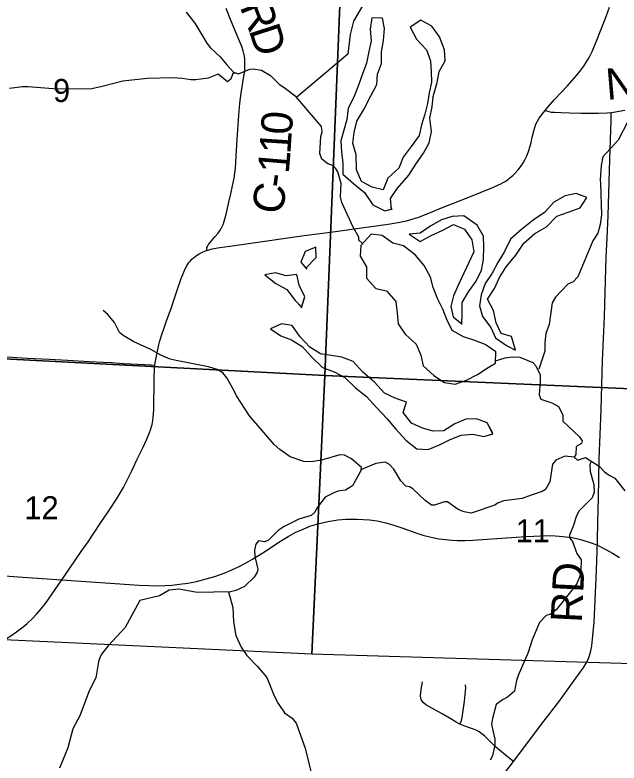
# Model space of a CAD drawing. Extents: x 0 to 34, y 0 to 22.
# Drawn here: x 4.017 to 5.115, y 17.641 to 19.003 of the extents above; entities that cross this region are included whole.
import ezdxf

# ---------------------------------------------------------------- set-up
doc = ezdxf.new("R2010")
doc.units = 0
for name, color, linetype in [('GM_X_County_Road', 7, 'Continuous'), ('GM_X_County_Road_Text', 7, 'Continuous'), ('GM_X_Minor_Lake', 7, 'Continuous'), ('GM_X_Minor_River', 7, 'Continuous'), ('GM_X_Rail_Line', 7, 'Continuous'), ('GM_X_Section', 7, 'Continuous'), ('GM_X_Section_Text', 7, 'Continuous'), ('GM_X_State_Route', 7, 'Continuous'), ('GM_X_Township_Road', 7, 'Continuous')]:
    doc.layers.add(name, color=color, linetype=linetype)

msp = doc.modelspace()

# ---------------------------------------------------------------- linework, layer by layer
at = {"layer": 'GM_X_County_Road'}
for points in [[(4.3655, 18.5744), (4.3655, 18.5774), (4.3658, 18.5797), (4.3666, 18.5814), (4.3689, 18.5853), (4.374, 18.5919), (4.3802, 18.5989), (4.3861, 18.606), (4.3896, 18.611), (4.3926, 18.6157), (4.3953, 18.6216), (4.398, 18.6295), (4.401, 18.6401), (4.4059, 18.6625), (4.4094, 18.6776), (4.4123, 18.6919), (4.4151, 18.7059), (4.4165, 18.7151), (4.4178, 18.7239), (4.4185, 18.7345), (4.419, 18.7462), (4.4207, 18.7772), (4.4236, 18.8206), (4.4255, 18.8423), (4.4278, 18.8608), (4.4327, 18.8915), (4.4345, 18.9017), (4.435, 18.9099), (4.435, 18.916), (4.4348, 18.9237), (4.4336, 18.9308), (4.4318, 18.9375), (4.4291, 18.9456), (4.4239, 18.9587), (4.4099, 18.9919), (4.4008, 19.0151)], [(4.9808, 18.8289), (4.9877, 18.8273), (4.9918, 18.8263), (4.9978, 18.8259), (5.0104, 18.8253), (5.0256, 18.8251), (5.0461, 18.8243), (5.0651, 18.8243), (5.0783, 18.8245), (5.0939, 18.8251), (5.101, 18.8258)], [(5.101, 18.8258), (5.1057, 18.8263), (5.126, 18.8297)], [(5.0762, 18.0453), (5.0771, 18.0802), (5.078, 18.123), (5.0796, 18.1943), (5.0828, 18.2841), (5.0855, 18.3739), (5.0888, 18.4539), (5.092, 18.5618), (5.094, 18.5969), (5.0956, 18.6378), (5.0986, 18.74), (5.1013, 18.8108), (5.1011, 18.822), (5.101, 18.8258)], [(4.9235, 17.6434), (4.9789, 17.7169), (5.0059, 17.7525), (5.0448, 17.8062), (5.0503, 17.8138), (5.0553, 17.8216), (5.0582, 17.8271), (5.0606, 17.8329), (5.0625, 17.8388), (5.064, 17.8449), (5.0657, 17.854), (5.0681, 17.8724), (5.0704, 17.8971), (5.0741, 17.9775), (5.0753, 18.0085), (5.0762, 18.0453)], [(4.9075, 17.6233), (4.9235, 17.6434)]]:
    msp.add_lwpolyline(points, dxfattribs=at)
at = {"layer": 'GM_X_Minor_Lake'}
for points in [[(4.7016, 18.6496), (4.6999, 18.6686), (4.7124, 18.6879), (4.7332, 18.7111), (4.7461, 18.7312), (4.7597, 18.7513), (4.7703, 18.7703), (4.7741, 18.7908), (4.7714, 18.8154), (4.7756, 18.8359), (4.7775, 18.8549), (4.7847, 18.8799), (4.7881, 18.9), (4.7994, 18.9198), (4.7979, 18.9395), (4.7888, 18.9634), (4.7748, 18.9827), (4.7552, 18.9937), (4.7355, 18.9808), (4.7472, 18.9592), (4.7654, 18.9395), (4.7726, 18.9194), (4.7737, 18.8996), (4.7744, 18.8807), (4.7703, 18.8613), (4.7673, 18.842), (4.762, 18.8226), (4.7559, 18.8029), (4.7521, 18.7835), (4.7374, 18.7634), (4.7226, 18.7441), (4.7147, 18.724), (4.695, 18.7058), (4.6863, 18.6849), (4.6666, 18.6894), (4.6469, 18.6997), (4.6378, 18.7213), (4.6371, 18.7482), (4.6314, 18.7699), (4.6337, 18.7892), (4.6382, 18.8097), (4.6511, 18.8309), (4.664, 18.8556), (4.6746, 18.8765), (4.6761, 18.8955), (4.6833, 18.9148), (4.6836, 18.9357), (4.6867, 18.9565), (4.6889, 18.9782), (4.6852, 18.9971), (4.6659, 18.9979), (4.6625, 18.977), (4.6647, 18.9562), (4.6606, 18.9364), (4.656, 18.9152), (4.6481, 18.8939), (4.6416, 18.875), (4.6329, 18.8537), (4.6227, 18.8332), (4.6204, 18.8127), (4.6151, 18.7934), (4.6091, 18.774), (4.6106, 18.7539), (4.6129, 18.7334), (4.6129, 18.7133), (4.6322, 18.6963), (4.6526, 18.6799), (4.6673, 18.6576), (4.6893, 18.6466)], [(4.7018, 18.6481), (4.6999, 18.6686), (4.7124, 18.6879), (4.7332, 18.7111), (4.7461, 18.7312), (4.7597, 18.7513), (4.7703, 18.7703), (4.7741, 18.7908), (4.7714, 18.8154), (4.7756, 18.8359), (4.7775, 18.8549), (4.7847, 18.8799), (4.7881, 18.9), (4.7994, 18.9198), (4.7979, 18.9395), (4.7888, 18.9634), (4.7748, 18.9827), (4.7552, 18.9937), (4.7355, 18.9808), (4.7472, 18.9592), (4.7654, 18.9395), (4.7726, 18.9194), (4.7737, 18.8996), (4.7744, 18.8807), (4.7703, 18.8613), (4.7673, 18.842), (4.762, 18.8226), (4.7559, 18.8029), (4.7521, 18.7835), (4.7374, 18.7634), (4.7226, 18.7441), (4.7147, 18.724), (4.695, 18.7058), (4.6863, 18.6849), (4.6666, 18.6894), (4.6469, 18.6997), (4.6378, 18.7213), (4.6371, 18.7482), (4.6314, 18.7699), (4.6337, 18.7892), (4.6382, 18.8097), (4.6511, 18.8309), (4.664, 18.8556), (4.6746, 18.8765), (4.6761, 18.8955), (4.6833, 18.9148), (4.6836, 18.9357), (4.6867, 18.9565), (4.6889, 18.9782), (4.6852, 18.9971), (4.6659, 18.9979), (4.6625, 18.977), (4.6647, 18.9562), (4.6606, 18.9364), (4.656, 18.9152), (4.6481, 18.8939), (4.6416, 18.875), (4.6329, 18.8537), (4.6227, 18.8332), (4.6204, 18.8127), (4.6151, 18.7934), (4.6091, 18.774), (4.6106, 18.7539), (4.6129, 18.7334), (4.6129, 18.7133), (4.6322, 18.6963), (4.6526, 18.6799), (4.6673, 18.6576), (4.6893, 18.6466), (4.7033, 18.65)], [(5.0374, 18.6777), (5.0177, 18.6736), (4.9969, 18.6622), (4.9799, 18.6432), (4.9595, 18.6295), (4.9383, 18.6125), (4.9182, 18.5946), (4.9069, 18.5722), (4.8951, 18.5525), (4.8849, 18.5332), (4.872, 18.5142), (4.8648, 18.4937), (4.8618, 18.4732), (4.8671, 18.4542), (4.8823, 18.4341), (4.8906, 18.4152), (4.911, 18.4015), (4.9269, 18.3928)], [(4.9269, 18.3928), (4.9201, 18.4178), (4.9008, 18.4231), (4.8921, 18.4425), (4.8872, 18.4649), (4.8762, 18.4857), (4.8887, 18.5051), (4.8982, 18.5252), (4.9099, 18.5442), (4.9277, 18.5658), (4.942, 18.5874), (4.9621, 18.6053), (4.9837, 18.6174), (5.0022, 18.6368), (5.023, 18.644), (5.0446, 18.6516), (5.0567, 18.6705), (5.0374, 18.6777), (5.0177, 18.6736), (4.9969, 18.6622), (4.9799, 18.6432), (4.9595, 18.6295), (4.9383, 18.6125), (4.9182, 18.5946), (4.9069, 18.5722), (4.8951, 18.5525), (4.8849, 18.5332), (4.872, 18.5142), (4.8648, 18.4937), (4.8618, 18.4732), (4.8671, 18.4542), (4.8823, 18.4341), (4.8906, 18.4152), (4.911, 18.4015), (4.9269, 18.3928)], [(4.9269, 18.3928), (4.9201, 18.4178), (4.9008, 18.4231), (4.8921, 18.4425), (4.8872, 18.4649), (4.8762, 18.4857), (4.8887, 18.5051), (4.8982, 18.5252), (4.9099, 18.5442), (4.9277, 18.5658), (4.942, 18.5874), (4.9621, 18.6053), (4.9837, 18.6174), (5.0022, 18.6368), (5.023, 18.644), (5.0446, 18.6516), (5.0567, 18.6705), (5.0374, 18.6777)], [(4.6893, 18.6466), (4.7016, 18.6496)], [(4.8297, 18.4405), (4.83, 18.458), (4.8304, 18.4793), (4.8418, 18.499), (4.8558, 18.5184), (4.8652, 18.5381), (4.869, 18.5578), (4.8698, 18.5806), (4.869, 18.6003), (4.8573, 18.6204), (4.8331, 18.6371), (4.8119, 18.636), (4.7926, 18.6299), (4.7733, 18.6193), (4.7536, 18.606), (4.7339, 18.6037), (4.7536, 18.5904), (4.774, 18.6014), (4.7952, 18.6113), (4.8145, 18.6215), (4.8342, 18.6132), (4.8475, 18.5939), (4.8512, 18.5715), (4.8425, 18.5525), (4.8334, 18.5328), (4.8236, 18.5123), (4.8141, 18.4918), (4.8092, 18.4724), (4.8138, 18.4531)], [(4.8297, 18.4414), (4.83, 18.458), (4.8304, 18.4793), (4.8418, 18.499), (4.8558, 18.5184), (4.8652, 18.5381), (4.869, 18.5578), (4.8698, 18.5806), (4.869, 18.6003), (4.8573, 18.6204), (4.8331, 18.6371), (4.8119, 18.636), (4.7926, 18.6299), (4.7733, 18.6193), (4.7536, 18.606), (4.7339, 18.6037), (4.7536, 18.5904), (4.774, 18.6014), (4.7952, 18.6113), (4.8145, 18.6215), (4.8342, 18.6132), (4.8475, 18.5939), (4.8512, 18.5715), (4.8425, 18.5525), (4.8334, 18.5328), (4.8236, 18.5123), (4.8141, 18.4918), (4.8092, 18.4724), (4.8138, 18.4531), (4.83, 18.4402)], [(4.8913, 18.3894), (4.8717, 18.403), (4.8516, 18.411), (4.8323, 18.4167), (4.8119, 18.4284), (4.802, 18.4485), (4.7948, 18.4675), (4.785, 18.4869), (4.7771, 18.507), (4.7725, 18.5259), (4.7608, 18.5468), (4.7453, 18.5658), (4.7233, 18.5828), (4.7037, 18.5874), (4.6844, 18.6018), (4.6647, 18.6037), (4.6458, 18.5836), (4.6443, 18.5639), (4.656, 18.5445), (4.656, 18.524), (4.673, 18.505), (4.6927, 18.5005), (4.7097, 18.4815), (4.7116, 18.4603), (4.7135, 18.4409), (4.7267, 18.422), (4.7464, 18.4034), (4.7551, 18.3833), (4.7593, 18.3643), (4.7786, 18.3465), (4.7982, 18.334), (4.8175, 18.3306), (4.838, 18.3378), (4.8577, 18.3484), (4.8773, 18.3613), (4.8906, 18.3693)], [(4.8906, 18.3693), (4.8913, 18.3894), (4.8717, 18.403), (4.8516, 18.411), (4.8323, 18.4167), (4.8119, 18.4284), (4.802, 18.4485), (4.7948, 18.4675), (4.785, 18.4869), (4.7771, 18.507), (4.7725, 18.5259), (4.7608, 18.5468), (4.7453, 18.5658), (4.7233, 18.5828), (4.7037, 18.5874), (4.6844, 18.6018), (4.6647, 18.6037), (4.6458, 18.5836), (4.6443, 18.5639), (4.656, 18.5445), (4.656, 18.524), (4.673, 18.505), (4.6927, 18.5005), (4.7097, 18.4815), (4.7116, 18.4603), (4.7135, 18.4409), (4.7267, 18.422), (4.7464, 18.4034), (4.7551, 18.3833), (4.7593, 18.3643), (4.7786, 18.3465), (4.7982, 18.334), (4.8175, 18.3306), (4.838, 18.3378), (4.8577, 18.3484), (4.8773, 18.3613), (4.8906, 18.3693), (4.8906, 18.3707)], [(4.5458, 18.5422), (4.5648, 18.5616), (4.564, 18.5805), (4.5444, 18.5722), (4.5368, 18.5532)], [(4.5451, 18.5414), (4.5648, 18.5616), (4.564, 18.5805), (4.5444, 18.5722), (4.5368, 18.5532), (4.5474, 18.5403)], [(4.5368, 18.5532), (4.5458, 18.5422)], [(4.5436, 18.4898), (4.5334, 18.5111), (4.5296, 18.5304), (4.5099, 18.5282), (4.4903, 18.5335), (4.471, 18.5297), (4.491, 18.5141), (4.5114, 18.5031), (4.5262, 18.4834), (4.538, 18.4712)], [(4.5376, 18.4697), (4.5436, 18.4898), (4.5334, 18.5111), (4.5296, 18.5304), (4.5099, 18.5282), (4.4903, 18.5335), (4.471, 18.5297), (4.491, 18.5141), (4.5114, 18.5031), (4.5262, 18.4834), (4.5376, 18.4716)], [(4.538, 18.4712), (4.5436, 18.4898)], [(4.8138, 18.4531), (4.8297, 18.4405)], [(4.8861, 18.2406), (4.8758, 18.2604), (4.8561, 18.2676), (4.8365, 18.2668), (4.8168, 18.2585), (4.7967, 18.2459), (4.7774, 18.2452), (4.7581, 18.2509), (4.7377, 18.2596), (4.7226, 18.2789), (4.729, 18.2983), (4.7082, 18.3051), (4.6889, 18.3146), (4.6707, 18.3343), (4.6495, 18.3529), (4.6321, 18.3719), (4.6113, 18.3798), (4.592, 18.3832), (4.5724, 18.3863), (4.5531, 18.3984), (4.5345, 18.4174), (4.5209, 18.4375), (4.5016, 18.4409), (4.4812, 18.4314), (4.5005, 18.4189), (4.5198, 18.4113), (4.5391, 18.3992), (4.5568, 18.3798), (4.5761, 18.3612), (4.5973, 18.3533), (4.6166, 18.343), (4.6359, 18.3241), (4.656, 18.3081), (4.6741, 18.288), (4.6938, 18.2679), (4.7097, 18.249), (4.7275, 18.2289), (4.7479, 18.2133), (4.768, 18.2118), (4.7888, 18.2201), (4.8085, 18.23), (4.8285, 18.238), (4.8497, 18.2395), (4.8694, 18.2353)], [(4.8856, 18.2414), (4.8758, 18.2604), (4.8561, 18.2676), (4.8365, 18.2668), (4.8168, 18.2585), (4.7967, 18.2459), (4.7774, 18.2452), (4.7581, 18.2509), (4.7377, 18.2596), (4.7226, 18.2789), (4.729, 18.2983), (4.7082, 18.3051), (4.6889, 18.3146), (4.6707, 18.3343), (4.6495, 18.3529), (4.6321, 18.3719), (4.6113, 18.3798), (4.592, 18.3832), (4.5724, 18.3863), (4.5531, 18.3984), (4.5345, 18.4174), (4.5209, 18.4375), (4.5016, 18.4409), (4.4812, 18.4314), (4.5005, 18.4189), (4.5198, 18.4113), (4.5391, 18.3992), (4.5568, 18.3798), (4.5761, 18.3612), (4.5973, 18.3533), (4.6166, 18.343), (4.6359, 18.3241), (4.656, 18.3081), (4.6741, 18.288), (4.6938, 18.2679), (4.7097, 18.249), (4.7275, 18.2289), (4.7479, 18.2133), (4.768, 18.2118), (4.7888, 18.2201), (4.8085, 18.23), (4.8285, 18.238), (4.8497, 18.2395), (4.8694, 18.2353), (4.8862, 18.2406)], [(4.8906, 18.3693), (4.8913, 18.3894)], [(4.8694, 18.2353), (4.8861, 18.2406)]]:
    msp.add_lwpolyline(points, dxfattribs=at)
at = {"layer": 'GM_X_Minor_River'}
for points in [[(4.6591, 19.0379), (4.6325, 18.9919), (4.6262, 18.9675), (4.6222, 18.9318), (4.5291, 18.8535)], [(4.3278, 19.0084), (4.3438, 18.9883), (4.3656, 18.9516), (4.3717, 18.9437), (4.3899, 18.9267), (4.4017, 18.9124), (4.4143, 18.8992), (4.4234, 18.8962), (4.4441, 18.9043), (4.4498, 18.905), (4.4653, 18.9025), (4.4816, 18.8931), (4.4976, 18.8765), (4.5082, 18.8697), (4.5291, 18.8535)], [(4.4202, 18.8972), (4.4131, 18.8965), (4.409, 18.8862), (4.4034, 18.8812), (4.3863, 18.8956), (4.3678, 18.8883), (4.3459, 18.8847), (4.3364, 18.8847), (4.3209, 18.8872), (4.3035, 18.8887), (4.2569, 18.8876), (4.2127, 18.8828), (4.1753, 18.8731), (4.1564, 18.8688), (4.0936, 18.8681), (4.0403, 18.8724), (4.0304, 18.8723), (4.0066, 18.8695)], [(4.649, 18.5871), (4.6424, 18.593), (4.642, 18.5983), (4.6317, 18.6164), (4.611, 18.6615), (4.6087, 18.6717), (4.6097, 18.6964), (4.6039, 18.7173), (4.5997, 18.7244), (4.5948, 18.729), (4.5857, 18.732), (4.5751, 18.7403), (4.5709, 18.7509), (4.573, 18.7816), (4.5752, 18.7904), (4.574, 18.8002), (4.5672, 18.8085), (4.5275, 18.8548)], [(5.1312, 18.809), (5.114, 18.7751), (5.0858, 18.7446), (5.0828, 18.729), (5.081, 18.7028), (5.0815, 18.6964), (5.0833, 18.6391), (5.0814, 18.6216), (5.0766, 18.6056), (5.0676, 18.5919), (5.0407, 18.5265), (5.032, 18.5169), (5.0226, 18.5127), (5.0109, 18.5009), (5, 18.4894), (4.994, 18.4788), (4.9882, 18.4393), (4.9826, 18.4229), (4.9804, 18.4066), (4.9805, 18.391), (4.9696, 18.3579)], [(4.6463, 18.1746), (4.6467, 18.1789), (4.6289, 18.1947), (4.616, 18.2015), (4.6076, 18.2022), (4.5744, 18.1925), (4.5562, 18.1894), (4.5422, 18.1897), (4.5172, 18.1986), (4.4983, 18.2118), (4.4884, 18.2209), (4.4435, 18.273), (4.4198, 18.3097), (4.4156, 18.3188), (4.4023, 18.3426), (4.395, 18.3517), (4.3844, 18.3573), (4.3689, 18.3625), (4.3098, 18.374), (4.2988, 18.3766), (4.2818, 18.3833), (4.2636, 18.3942), (4.2328, 18.4077), (4.2135, 18.4194), (4.207, 18.425), (4.1975, 18.4432), (4.1857, 18.4575), (4.1773, 18.4647)], [(4.8908, 18.3746), (4.8909, 18.3734), (4.9086, 18.3788), (4.9219, 18.3808), (4.9351, 18.3801), (4.9586, 18.3704), (4.9643, 18.364), (4.9723, 18.3477), (4.972, 18.3359), (4.9703, 18.3112), (4.9733, 18.3033), (4.9934, 18.2969), (5.0052, 18.2902), (5.0132, 18.275), (5.0132, 18.2633), (5.0436, 18.235), (5.0482, 18.2274), (5.0471, 18.2225), (5.0377, 18.2175), (5.037, 18.203), (5.034, 18.1977), (5.0397, 18.1921), (5.0544, 18.1971), (5.0791, 18.1816), (5.089, 18.1714), (5.0977, 18.165), (5.1079, 18.1598), (5.1258, 18.1367)], [(5.034, 18.1977), (5.0166, 18.1995), (5.0007, 18.1926), (4.9943, 18.185), (4.9896, 18.1531), (4.9817, 18.139), (4.9757, 18.1355), (4.9557, 18.1286), (4.9394, 18.1224), (4.9058, 18.1184), (4.8956, 18.1146), (4.8895, 18.1104), (4.8465, 18.0957), (4.834, 18.0983), (4.8226, 18.1028), (4.8143, 18.1088), (4.8033, 18.1167), (4.798, 18.1167), (4.7795, 18.1105), (4.7742, 18.1105), (4.7628, 18.1192), (4.7403, 18.1403), (4.7343, 18.1437), (4.7278, 18.1448), (4.7187, 18.155), (4.7061, 18.1762), (4.6981, 18.1845), (4.6902, 18.189), (4.6728, 18.1862), (4.6467, 18.1754), (4.6306, 18.1457), (4.6178, 18.1377), (4.6038, 18.1357), (4.5966, 18.133), (4.5808, 18.125), (4.5669, 18.1067), (4.5616, 18.0968), (4.5552, 18.0918), (4.5329, 18.0848), (4.5061, 18.0714), (4.4956, 18.0641), (4.4779, 18.047), (4.4707, 18.0435), (4.4594, 18.0453), (4.4549, 18.0396), (4.4526, 18.0282), (4.4527, 18.0172), (4.4581, 17.9941), (4.457, 17.9884), (4.4517, 17.9792), (4.4341, 17.9621), (4.4182, 17.9548), (4.4084, 17.9524), (4.3478, 17.9517), (4.3153, 17.9572), (4.2971, 17.9556), (4.2798, 17.9456), (4.2439, 17.9371), (4.2169, 17.8876), (4.186, 17.8544), (4.174, 17.8391), (4.1706, 17.8315), (4.1684, 17.8254), (4.1636, 17.7958), (4.1513, 17.7726), (4.1345, 17.7266), (4.1221, 17.703), (4.1128, 17.6687), (4.0975, 17.6315)], [(5.0648, 18.1906), (5.0621, 18.1838), (5.0632, 18.1717), (5.0698, 18.1478), (5.0702, 18.1341), (5.0665, 18.1235), (5.0428, 18.1002), (5.0372, 18.0895), (5.0335, 18.0755), (5.0256, 18.0561), (5.026, 18.0504), (5.0306, 18.044), (5.039, 18.0227), (5.0463, 18.0106), (5.046, 17.9913), (5.0438, 17.9795), (5.0385, 17.9677), (5.0344, 17.962), (5.0013, 17.9201), (4.99, 17.9116), (4.9832, 17.9097), (4.9708, 17.8967), (4.9573, 17.8651), (4.9499, 17.8419), (4.9319, 17.8001), (4.929, 17.7913), (4.9256, 17.772), (4.9128, 17.7605), (4.9034, 17.7559), (4.8917, 17.7475), (4.885, 17.722), (4.8836, 17.711), (4.8898, 17.6845), (4.8898, 17.6742), (4.8854, 17.6541), (4.8813, 17.6461)], [(4.4053, 17.9524), (4.4131, 17.924), (4.4143, 17.8982), (4.4186, 17.8732), (4.4278, 17.8516), (4.4381, 17.8368), (4.4578, 17.8168), (4.475, 17.7964), (4.488, 17.7635), (4.4956, 17.7491), (4.5071, 17.7324), (4.5207, 17.7223), (4.5283, 17.7132), (4.5448, 17.6677), (4.558, 17.6131)]]:
    msp.add_lwpolyline(points, dxfattribs=at)
at = {"layer": 'GM_X_Rail_Line'}
msp.add_lwpolyline([(3.9068, 17.9883), (4.0309, 17.9795), (4.2428, 17.965), (4.2601, 17.9641), (4.2752, 17.9635), (4.2898, 17.9641), (4.3017, 17.9648), (4.3161, 17.9663), (4.3308, 17.9684), (4.3467, 17.9715), (4.3643, 17.9761), (4.3804, 17.9808), (4.397, 17.9868), (4.4112, 17.9928), (4.4232, 17.9983), (4.4361, 18.005), (4.4484, 18.0121), (4.4673, 18.0237), (4.5013, 18.0462), (4.5137, 18.0535), (4.5278, 18.0612), (4.5407, 18.067), (4.5532, 18.0719), (4.5697, 18.0769), (4.5855, 18.0805), (4.6038, 18.0835), (4.6183, 18.0849), (4.6392, 18.0852), (4.6618, 18.0837), (4.6756, 18.0817), (4.6915, 18.0781), (4.7059, 18.074), (4.7221, 18.0684), (4.7458, 18.0601), (4.7585, 18.0561), (4.7736, 18.0519), (4.7877, 18.0493), (4.7996, 18.0477), (4.8117, 18.0468), (4.8209, 18.0462), (4.8356, 18.0461), (4.8493, 18.0467), (4.9457, 18.0533), (4.9605, 18.0541), (4.9843, 18.0549), (5.0001, 18.0545), (5.0133, 18.0536), (5.0298, 18.0513), (5.0435, 18.0484), (5.0612, 18.043), (5.0748, 18.0381), (5.0915, 18.03), (5.1038, 18.0231), (5.1162, 18.0152)], dxfattribs=at)
at = {"layer": 'GM_X_Section'}
for points in [[(4.6214, 19.3661), (4.58, 18.3465), (3.5763, 18.3989), (3.6257, 19.4083)], [(5.6189, 19.331), (5.5833, 18.3028), (4.58, 18.3465), (4.6214, 19.3661)], [(3.5763, 18.3989), (4.58, 18.3465), (4.5566, 17.8394), (3.5534, 17.8861)], [(5.5833, 18.3028), (5.5625, 17.8089), (4.5566, 17.8394), (4.58, 18.3465)]]:
    msp.add_lwpolyline(points, close=True, dxfattribs=at)
at = {"layer": 'GM_X_State_Route'}
for points in [[(4.2138, 18.1426), (4.2196, 18.1536), (4.2293, 18.173), (4.2382, 18.1927), (4.2491, 18.2151), (4.2556, 18.2292), (4.2605, 18.2407), (4.2637, 18.2493), (4.2652, 18.2538), (4.2662, 18.2576), (4.2669, 18.261), (4.2674, 18.2646), (4.2682, 18.2709), (4.2686, 18.2763), (4.2691, 18.2859), (4.2695, 18.2976), (4.2698, 18.3262), (4.2699, 18.345), (4.2703, 18.3571), (4.2711, 18.3648), (4.2716, 18.3698), (4.2738, 18.3819), (4.2763, 18.394), (4.2784, 18.4026), (4.2803, 18.4099), (4.2845, 18.4228), (4.2874, 18.4318), (4.2917, 18.4446), (4.3011, 18.4706), (4.3061, 18.4853), (4.3112, 18.5002), (4.3191, 18.5234), (4.323, 18.5338), (4.3262, 18.5409), (4.3292, 18.5465), (4.331, 18.5493), (4.3329, 18.5521), (4.3357, 18.5554), (4.3385, 18.5584), (4.3414, 18.5609), (4.3441, 18.5632), (4.3466, 18.5649), (4.3519, 18.5683), (4.3575, 18.5713), (4.3633, 18.5737), (4.3655, 18.5744), (4.3693, 18.5755), (4.3754, 18.577), (4.3892, 18.5795), (4.4076, 18.5821), (4.4756, 18.5916), (4.5043, 18.5958), (4.5424, 18.6013), (4.5997, 18.6091), (4.6336, 18.6138), (4.6644, 18.618), (4.6952, 18.6223), (4.7135, 18.6254), (4.7287, 18.6285), (4.7407, 18.6317), (4.7495, 18.6345), (4.7726, 18.6434), (4.7927, 18.6516), (4.8359, 18.669), (4.8647, 18.6806), (4.8873, 18.6898), (4.8959, 18.6936), (4.9007, 18.6959), (4.9048, 18.698), (4.9084, 18.7001), (4.9124, 18.7031), (4.917, 18.7064), (4.922, 18.7105), (4.9261, 18.7145), (4.9321, 18.7213), (4.9379, 18.7288), (4.9413, 18.7339), (4.9444, 18.7392), (4.9483, 18.7476), (4.9514, 18.756), (4.9533, 18.7623), (4.9555, 18.771), (4.9576, 18.7804), (4.9603, 18.7919), (4.962, 18.7983), (4.9642, 18.8045), (4.967, 18.8096), (4.9704, 18.815), (4.976, 18.823), (4.9808, 18.8289), (4.9862, 18.8355), (4.9981, 18.849), (5.0215, 18.8743), (5.038, 18.8928), (5.046, 18.9023), (5.0515, 18.9097), (5.0565, 18.9175), (5.061, 18.9256), (5.0664, 18.9367), (5.0736, 18.9539), (5.0918, 19.0001), (5.0982, 19.0176)], [(3.984, 17.8574), (3.9934, 17.8627), (4.0092, 17.8725), (4.0194, 17.8795), (4.0318, 17.8888), (4.0389, 17.8947), (4.0478, 17.9032), (4.0562, 17.9123), (4.0643, 17.9217), (4.0719, 17.9315), (4.0845, 17.9491), (4.1071, 17.9822), (4.1267, 18.0106), (4.137, 18.0261), (4.1495, 18.0438), (4.1716, 18.0768), (4.186, 18.0986), (4.2011, 18.1213), (4.2138, 18.1426)]]:
    msp.add_lwpolyline(points, dxfattribs=at)
at = {"layer": 'GM_X_Township_Road'}
for points in [[(4.2711, 18.3648), (4.2646, 18.3652), (4.2402, 18.3667), (4.2141, 18.3678), (4.1921, 18.3694), (4.1772, 18.37), (4.1518, 18.3715), (4.1119, 18.3737), (4.0786, 18.3756), (4.0387, 18.3778), (3.9918, 18.3803), (3.9269, 18.3839), (3.9004, 18.3855)], [(4.8259, 17.7119), (4.819, 17.7154), (4.8113, 17.72), (4.7936, 17.7303), (4.7815, 17.737), (4.7696, 17.7437), (4.7642, 17.7471), (4.7593, 17.7511), (4.7571, 17.7536), (4.7556, 17.7565), (4.7548, 17.7597), (4.7546, 17.7629), (4.7549, 17.7692), (4.7559, 17.7786), (4.7578, 17.7888)], [(4.8259, 17.7119), (4.8287, 17.7181), (4.8303, 17.7238), (4.8342, 17.7533), (4.8361, 17.7715), (4.8365, 17.7775), (4.8361, 17.7835)], [(4.9235, 17.6434), (4.9119, 17.6527), (4.9012, 17.6616), (4.891, 17.6706), (4.8752, 17.6862), (4.8706, 17.6903), (4.8659, 17.6943), (4.8635, 17.6961), (4.8609, 17.6977), (4.8556, 17.7005), (4.8468, 17.7039), (4.8349, 17.7082), (4.8259, 17.7119)]]:
    msp.add_lwpolyline(points, dxfattribs=at)

# ---------------------------------------------------------------- texts
at = {"layer": 'GM_X_County_Road_Text'}
for s, height, rotation, p in [('R', 0.0568, 291.0215, (4.425, 19.0184)), ('D', 0.0568, 287.9523, (4.4415, 18.9756)), ('N', 0.0568, 4.9092, (5.0936, 18.8484)), ('0', 0.0568, 85.7498, (4.5199, 18.7837)), ('1', 0.0568, 86.259, (4.5176, 18.7489)), ('1', 0.0568, 85.2084, (4.5146, 18.7129)), ('-', 0.0568, 82.0597, (4.511, 18.6864)), ('C', 0.0568, 79.2151, (4.5018, 18.6375)), ('RD', 0.05682, 87.2056, (5.0477, 17.8956))]:
    msp.add_text(s, height=height, rotation=rotation, dxfattribs=at).set_placement(p)
at = {"layer": 'GM_X_Section_Text'}
for s, height, p in [('9', 0.0419, (4.0859, 18.8446)), ('12', 0.04186, (4.0338, 18.0849)), ('11', 0.04186, (4.9275, 18.0429))]:
    msp.add_text(s, height=height, rotation=0, dxfattribs=at).set_placement(p)

doc.saveas('drawing.dxf')
